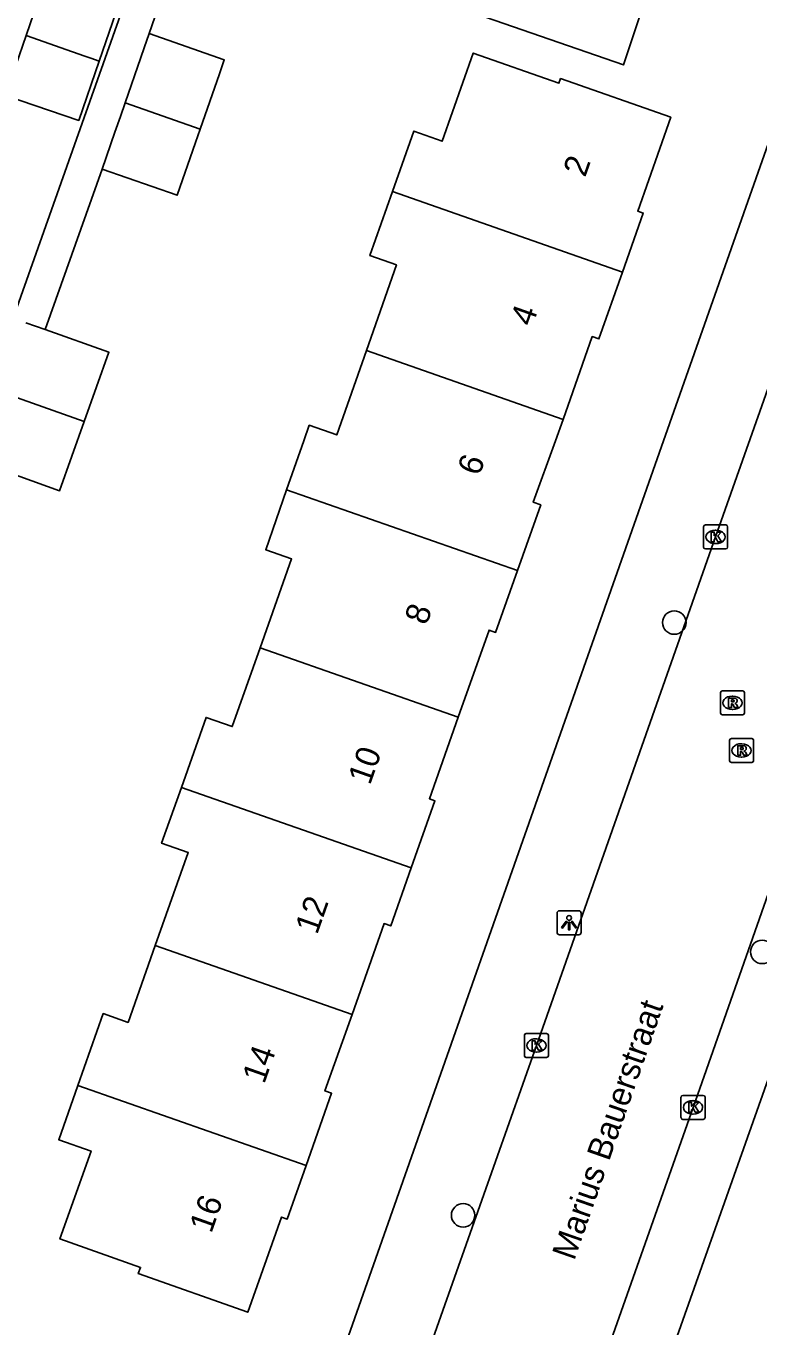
# Model space of a CAD drawing. Extents: x 163268 to 164360, y 381529 to 382285.
# Drawn here: x 163766.6 to 163797.1, y 381713.1 to 381767.3 of the extents above; entities that cross this region are included whole.
import ezdxf

# ---------------------------------------------------------------- set-up
doc = ezdxf.new("R2010")
doc.units = 0
for name, color, linetype in [('IMGEO_Boom', 7, 'Continuous'), ('IMGEO_Kolk', 7, 'Continuous'), ('IMGEO_Lichtpunt', 7, 'Continuous'), ('IMGEO_Openbare_ruimte_label', 7, 'Continuous'), ('IMGEO_Pand', 7, 'Continuous'), ('IMGEO_Pand_nummerreeks', 7, 'Continuous'), ('IMGEO_Rijbaan_lokaal_open', 7, 'Continuous'), ('IMGEO_Rioolput', 7, 'Continuous'), ('IMGEO_Voetpad_open', 7, 'Continuous')]:
    doc.layers.add(name, color=color, linetype=linetype)

msp = doc.modelspace()

# ---------------------------------------------------------------- linework, layer by layer
at = {"layer": 'IMGEO_Boom'}
for centre in [(163793.607, 381742.426), (163797.269, 381728.696), (163784.809, 381717.716)]:
    msp.add_circle(centre, 0.489, dxfattribs=at)
at = {"layer": 'IMGEO_Kolk'}
for p, q in [((163794.902, 381746.496), (163795.754, 381746.496)), ((163794.827, 381745.57), (163794.827, 381746.422)), ((163795.315, 381746.276), (163795.34, 381746.276)), ((163795.828, 381746.422), (163795.828, 381745.57)), ((163795.754, 381745.496), (163794.902, 381745.496)), ((163795.338, 381745.716), (163795.313, 381745.716)), ((163787.437, 381725.296), (163788.289, 381725.296)), ((163787.362, 381724.37), (163787.362, 381725.222)), ((163787.85, 381725.076), (163787.875, 381725.076)), ((163788.363, 381725.222), (163788.363, 381724.37)), ((163788.289, 381724.296), (163787.437, 381724.296)), ((163787.873, 381724.516), (163787.848, 381724.516)), ((163793.886, 381721.789), (163793.886, 381722.641)), ((163793.961, 381722.715), (163794.813, 381722.715)), ((163794.887, 381722.641), (163794.887, 381721.789)), ((163794.374, 381722.495), (163794.399, 381722.495)), ((163794.813, 381721.715), (163793.961, 381721.715)), ((163794.397, 381721.935), (163794.372, 381721.935))]:
    msp.add_line(p, q, dxfattribs=at)
for points in [[(163794.902, 381746.496), (163795.754, 381746.496)], [(163794.827, 381745.57), (163794.827, 381746.422)], [(163795.148, 381746.196), (163795.271, 381746.196), (163795.271, 381746.045), (163795.401, 381746.196), (163795.565, 381746.196), (163795.419, 381746.045), (163795.572, 381745.796), (163795.42, 381745.796), (163795.335, 381745.96), (163795.271, 381745.893), (163795.271, 381745.796), (163795.148, 381745.796), (163795.148, 381746.196)], [(163795.828, 381746.422), (163795.828, 381745.57)], [(163795.754, 381745.496), (163794.902, 381745.496)], [(163787.437, 381725.296), (163788.289, 381725.296)], [(163787.362, 381724.37), (163787.362, 381725.222)], [(163787.683, 381724.996), (163787.806, 381724.996), (163787.806, 381724.845), (163787.936, 381724.996), (163788.1, 381724.996), (163787.954, 381724.845), (163788.107, 381724.596), (163787.955, 381724.596), (163787.87, 381724.76), (163787.806, 381724.693), (163787.806, 381724.596), (163787.683, 381724.596), (163787.683, 381724.996)], [(163788.363, 381725.222), (163788.363, 381724.37)], [(163788.289, 381724.296), (163787.437, 381724.296)], [(163793.886, 381721.789), (163793.886, 381722.641)], [(163793.961, 381722.715), (163794.813, 381722.715)], [(163794.887, 381722.641), (163794.887, 381721.789)], [(163794.207, 381722.415), (163794.33, 381722.415), (163794.33, 381722.264), (163794.46, 381722.415), (163794.624, 381722.415), (163794.478, 381722.264), (163794.631, 381722.015), (163794.479, 381722.015), (163794.394, 381722.179), (163794.33, 381722.112), (163794.33, 381722.015), (163794.207, 381722.015), (163794.207, 381722.415)], [(163794.813, 381721.715), (163793.961, 381721.715)]]:
    msp.add_lwpolyline(points, dxfattribs=at)
for centre, start, end in [((163794.904, 381746.42), 91.552, 178.448), ((163794.904, 381746.42), 91.552, 178.448), ((163795.752, 381746.42), 1.552, 88.448), ((163795.752, 381746.42), 1.552, 88.448), ((163794.904, 381745.572), 181.552, 268.448), ((163794.904, 381745.572), 181.552, 268.448), ((163795.752, 381745.572), 271.552, 358.448), ((163795.752, 381745.572), 271.552, 358.448), ((163787.439, 381725.22), 91.552, 178.448), ((163787.439, 381725.22), 91.552, 178.448), ((163788.287, 381725.22), 1.552, 88.448), ((163788.287, 381725.22), 1.552, 88.448), ((163787.439, 381724.372), 181.552, 268.448), ((163787.439, 381724.372), 181.552, 268.448), ((163788.287, 381724.372), 271.552, 358.448), ((163788.287, 381724.372), 271.552, 358.448), ((163793.963, 381722.639), 91.552, 178.448), ((163793.963, 381722.639), 91.552, 178.448), ((163794.811, 381722.639), 1.552, 88.448), ((163794.811, 381722.639), 1.552, 88.448), ((163793.963, 381721.791), 181.552, 268.448), ((163793.963, 381721.791), 181.552, 268.448), ((163794.811, 381721.791), 271.552, 358.448), ((163794.811, 381721.791), 271.552, 358.448)]:
    msp.add_arc(centre, 0.0765, start, end, dxfattribs=at)
for centre, major_axis, ratio, start_param, end_param in [((163795.314, 381745.996), (-0.387, 0.002), 0.722429, 4.712389, 7.853982), ((163795.339, 381745.996), (-0.39, 0.002), 0.717154, 1.570796, 4.712389), ((163787.849, 381724.796), (-0.387, 0.002), 0.722429, 4.712389, 7.853982), ((163787.874, 381724.796), (-0.39, 0.002), 0.717154, 1.570796, 4.712389), ((163794.373, 381722.215), (-0.387, 0.002), 0.722429, 4.712389, 7.853982), ((163794.398, 381722.215), (-0.39, 0.002), 0.717154, 1.570796, 4.712389)]:
    msp.add_ellipse(centre, major_axis=major_axis, ratio=ratio, start_param=start_param, end_param=end_param, dxfattribs=at)
at = {"layer": 'IMGEO_Lichtpunt'}
for p, q in [((163788.727, 381730.316), (163788.727, 381729.509)), ((163788.727, 381730.316), (163788.727, 381729.509)), ((163789.629, 381730.411), (163788.821, 381730.411)), ((163789.629, 381730.411), (163788.821, 381730.411)), ((163789.723, 381729.509), (163789.723, 381730.316)), ((163789.723, 381729.509), (163789.723, 381730.316)), ((163788.821, 381729.415), (163789.629, 381729.415)), ((163788.821, 381729.415), (163789.629, 381729.415))]:
    msp.add_line(p, q, dxfattribs=at)
for points in [[(163789.101, 381729.98), (163789.14, 381729.952), (163788.952, 381729.69), (163788.914, 381729.717), (163789.101, 381729.98)], [(163789.203, 381729.932), (163789.25, 381729.932), (163789.25, 381729.61), (163789.203, 381729.61), (163789.203, 381729.932)], [(163789.313, 381729.952), (163789.351, 381729.979), (163789.538, 381729.717), (163789.499, 381729.689), (163789.313, 381729.952)]]:
    msp.add_lwpolyline(points, dxfattribs=at)
msp.add_circle((163789.226, 381730.114), 0.0994, dxfattribs=at)
for centre, start, end in [((163788.821, 381730.316), 90, 180), ((163788.821, 381730.316), 90, 180), ((163789.629, 381730.316), 0, 90), ((163789.629, 381730.316), 0, 90), ((163788.821, 381729.509), 180, 270), ((163788.821, 381729.509), 180, 270), ((163789.629, 381729.509), 270, 0), ((163789.629, 381729.509), 270, 360)]:
    msp.add_arc(centre, 0.0946, start, end, dxfattribs=at)
at = {"layer": 'IMGEO_Pand'}
for points in [[(163769.645, 381765.83), (163770.616, 381768.671), (163770.703, 381768.923), (163771.832, 381772.226), (163768.783, 381773.268), (163767.567, 381769.713), (163766.606, 381766.901)], [(163766.606, 381766.901), (163765.751, 381764.4), (163768.8, 381763.359), (163769.645, 381765.83)], [(163769.645, 381765.83), (163769.294, 381765.954), (163769.049, 381766.041), (163768.53, 381766.223), (163766.606, 381766.901)], [(163770.724, 381764.087), (163771.38, 381765.976), (163771.524, 381766.392), (163771.727, 381766.978)], [(163771.727, 381766.978), (163774.858, 381765.89), (163774.655, 381765.304), (163773.855, 381763)], [(163791.446, 381757.035), (163792.312, 381759.499), (163792.085, 381759.578), (163793.461, 381763.492), (163788.869, 381765.107), (163788.801, 381764.912), (163785.233, 381766.167), (163783.942, 381762.494), (163782.752, 381762.912), (163781.867, 381760.394)], [(163770.724, 381764.087), (163770.53, 381763.527), (163770.299, 381762.863), (163769.766, 381761.327)], [(163773.855, 381763), (163770.724, 381764.087)], [(163769.766, 381761.327), (163772.898, 381760.24), (163773.661, 381762.44), (163773.855, 381763)], [(163781.867, 381760.394), (163780.927, 381757.722), (163782.033, 381757.333), (163780.781, 381753.771)], [(163781.867, 381760.394), (163791.446, 381757.035)], [(163788.976, 381750.897), (163790.19, 381754.35), (163790.468, 381754.253), (163791.446, 381757.035)], [(163766.596, 381754.927), (163767.393, 381754.643)], [(163767.393, 381754.643), (163770.053, 381753.697), (163769.026, 381750.811)], [(163780.781, 381753.771), (163779.543, 381750.251), (163778.397, 381750.654), (163778.169, 381750), (163777.458, 381747.963)], [(163788.976, 381750.897), (163780.781, 381753.771)], [(163769.026, 381750.811), (163765.573, 381752.033)], [(163765.178, 381748.926), (163767.998, 381747.922), (163769.026, 381750.811)], [(163787.074, 381744.591), (163788.042, 381747.333), (163787.728, 381747.443), (163788.661, 381750), (163788.976, 381750.897)], [(163777.458, 381747.963), (163776.585, 381745.46), (163777.66, 381745.081), (163776.352, 381741.378)], [(163777.458, 381747.963), (163787.074, 381744.591)], [(163784.608, 381738.484), (163785.891, 381742.115), (163786.165, 381742.018), (163787.074, 381744.591)], [(163776.352, 381741.378), (163775.191, 381738.091), (163774.105, 381738.475), (163773.073, 381735.556)], [(163784.608, 381738.484), (163776.352, 381741.378)], [(163782.649, 381732.197), (163783.638, 381734.995), (163783.405, 381735.078), (163784.608, 381738.484)], [(163773.073, 381735.556), (163772.251, 381733.229), (163773.356, 381732.838), (163771.987, 381728.964)], [(163773.073, 381735.556), (163782.649, 381732.197)], [(163780.181, 381726.091), (163781.518, 381729.878), (163781.795, 381729.78), (163782.649, 381732.197)], [(163771.987, 381728.964), (163770.854, 381725.758), (163769.821, 381726.123), (163768.761, 381723.122)], [(163780.181, 381726.091), (163771.987, 381728.964)], [(163778.267, 381719.789), (163779.332, 381722.803), (163779.054, 381722.901), (163780.181, 381726.091)], [(163768.761, 381723.122), (163767.964, 381720.867), (163769.308, 381720.392), (163768.014, 381716.729), (163771.37, 381715.543), (163771.278, 381715.283), (163775.84, 381713.672), (163777.244, 381717.645), (163777.48, 381717.561), (163778.267, 381719.789)], [(163768.761, 381723.122), (163778.267, 381719.789)]]:
    msp.add_lwpolyline(points, dxfattribs=at)
at = {"layer": 'IMGEO_Rijbaan_lokaal_open'}
for points in [[(163780.903, 381705.075), (163781.038, 381705.454), (163787.863, 381724.796), (163795.328, 381745.996), (163802.49, 381766.272), (163802.834, 381767.295)], [(163787.28, 381701.743), (163787.425, 381702.556), (163787.562, 381702.837), (163794.387, 381722.215), (163797.797, 381731.907)]]:
    msp.add_lwpolyline(points, dxfattribs=at)
at = {"layer": 'IMGEO_Rioolput'}
for p, q in [((163795.531, 381738.654), (163795.531, 381739.506)), ((163795.606, 381739.58), (163796.458, 381739.58)), ((163796.532, 381739.506), (163796.532, 381738.654)), ((163796.019, 381739.36), (163796.044, 381739.36)), ((163796.458, 381738.58), (163795.606, 381738.58)), ((163796.042, 381738.8), (163796.017, 381738.8)), ((163795.91, 381736.668), (163795.91, 381737.52)), ((163795.985, 381737.594), (163796.837, 381737.594)), ((163796.398, 381737.374), (163796.423, 381737.374)), ((163796.911, 381737.52), (163796.911, 381736.668)), ((163796.421, 381736.814), (163796.396, 381736.814)), ((163796.837, 381736.594), (163795.985, 381736.594))]:
    msp.add_line(p, q, dxfattribs=at)
for points in [[(163795.531, 381738.654), (163795.531, 381739.506)], [(163795.606, 381739.58), (163796.458, 381739.58)], [(163796.532, 381739.506), (163796.532, 381738.654)], [(163796.12, 381739.278), (163795.868, 381739.28), (163795.868, 381738.88)], [(163795.868, 381738.88), (163795.992, 381738.88), (163795.992, 381739.042), (163796.003, 381739.042)], [(163796.046, 381739.199), (163795.992, 381739.199), (163795.992, 381739.118)], [(163795.992, 381739.118), (163796.044, 381739.118)], [(163796.05, 381739.013), (163796.121, 381738.88), (163796.261, 381738.88), (163796.196, 381739.006)], [(163796.458, 381738.58), (163795.606, 381738.58)], [(163795.91, 381736.668), (163795.91, 381737.52)], [(163795.985, 381737.594), (163796.837, 381737.594)], [(163796.499, 381737.292), (163796.247, 381737.294), (163796.247, 381736.894)], [(163796.425, 381737.213), (163796.371, 381737.213), (163796.371, 381737.132)], [(163796.911, 381737.52), (163796.911, 381736.668)], [(163796.247, 381736.894), (163796.371, 381736.894), (163796.371, 381737.056), (163796.382, 381737.056)], [(163796.371, 381737.132), (163796.423, 381737.132)], [(163796.429, 381737.027), (163796.5, 381736.894), (163796.64, 381736.894), (163796.575, 381737.02)], [(163796.837, 381736.594), (163795.985, 381736.594)]]:
    msp.add_lwpolyline(points, dxfattribs=at)
for centre, radius, start, end in [((163795.608, 381739.504), 0.0765, 91.552, 178.448), ((163795.608, 381739.504), 0.0765, 91.552, 178.448), ((163796.456, 381739.504), 0.0765, 1.552, 88.448), ((163796.456, 381739.504), 0.0765, 1.552, 88.448), ((163796.002, 381738.989), 0.0533, 26.0293, 88.6989), ((163796.028, 381739.307), 0.19, 274.7715, 282.9687), ((163796.052, 381739.103), 0.0964, 77.0061, 93.1865), ((163796.066, 381739.16), 0.0378, 276.6634, 79.6772), ((163796.119, 381739.168), 0.109, 350.3612, 89.416), ((163796.117, 381739.168), 0.112, 277.5842, 350.9817), ((163796.101, 381738.953), 0.108, 29.5134, 73.7905), ((163795.608, 381738.656), 0.0765, 181.552, 268.448), ((163795.608, 381738.656), 0.0765, 181.552, 268.448), ((163796.456, 381738.656), 0.0765, 271.552, 358.448), ((163796.456, 381738.656), 0.0765, 271.552, 358.448), ((163795.987, 381737.518), 0.0765, 91.552, 178.448), ((163795.987, 381737.518), 0.0765, 91.552, 178.448), ((163796.431, 381737.117), 0.0964, 77.0061, 93.1865), ((163796.445, 381737.174), 0.0378, 276.6634, 79.6772), ((163796.498, 381737.182), 0.109, 350.3612, 89.416), ((163796.835, 381737.518), 0.0765, 1.552, 88.448), ((163796.835, 381737.518), 0.0765, 1.552, 88.448), ((163795.987, 381736.67), 0.0765, 181.552, 268.448), ((163795.987, 381736.67), 0.0765, 181.552, 268.448), ((163796.381, 381737.003), 0.0533, 26.0293, 88.6989), ((163796.407, 381737.321), 0.19, 274.7715, 282.9687), ((163796.496, 381737.182), 0.112, 277.5842, 350.9817), ((163796.48, 381736.967), 0.108, 29.5134, 73.7905), ((163796.835, 381736.67), 0.0765, 271.552, 358.448), ((163796.835, 381736.67), 0.0765, 271.552, 358.448)]:
    msp.add_arc(centre, radius, start, end, dxfattribs=at)
for centre, major_axis, ratio, start_param, end_param in [((163796.018, 381739.08), (-0.387, 0.002), 0.722429, 4.712389, 7.853982), ((163796.043, 381739.08), (-0.39, 0.002), 0.717154, 1.570796, 4.712389), ((163796.397, 381737.094), (-0.387, 0.002), 0.722429, 4.712389, 7.853982), ((163796.422, 381737.094), (-0.39, 0.002), 0.717154, 1.570796, 4.712389)]:
    msp.add_ellipse(centre, major_axis=major_axis, ratio=ratio, start_param=start_param, end_param=end_param, dxfattribs=at)
at = {"layer": 'IMGEO_Voetpad_open'}
for points in [[(163759.849, 381776.496), (163771.532, 381772.501), (163772.137, 381772.294), (163766.06, 381755.118)], [(163771.727, 381766.978), (163773.445, 381771.929), (163791.485, 381765.67), (163794.313, 381774.123)], [(163799.834, 381768.991), (163793.157, 381750), (163777.847, 381706.456)], [(163767.393, 381754.643), (163769.766, 381761.327)], [(163800.206, 381731.005), (163790.326, 381703.056)]]:
    msp.add_lwpolyline(points, dxfattribs=at)

# ---------------------------------------------------------------- texts
at = {"layer": 'IMGEO_Openbare_ruimte_label'}
msp.add_text('Marius Bauerstraat', height=1, rotation=70.7316, dxfattribs=at).set_placement((163789.437, 381715.797))
at = {"layer": 'IMGEO_Pand_nummerreeks'}
for s, p in [('2', (163789.892, 381760.957)), ('4', (163787.69, 381754.732)), ('6', (163785.487, 381748.504)), ('8', (163783.286, 381742.281)), ('10', (163780.929, 381735.618)), ('12', (163778.725, 381729.385)), ('14', (163776.523, 381723.16)), ('16', (163774.32, 381716.933))]:
    msp.add_text(s, height=1, rotation=70.5217, dxfattribs=at).set_placement(p)

doc.saveas('drawing.dxf')
